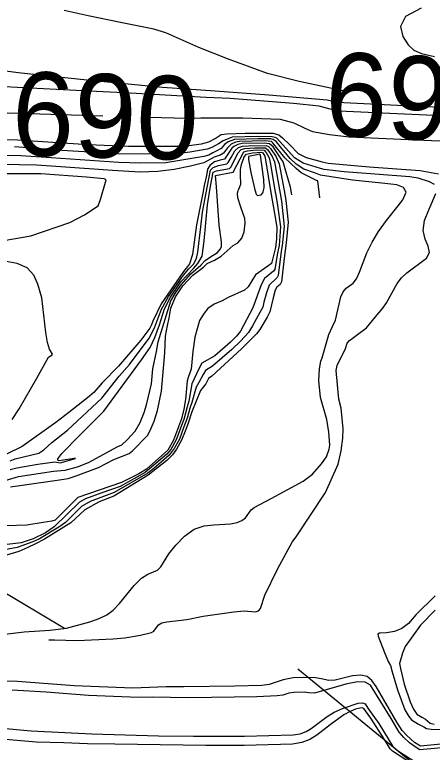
# Model space of a CAD drawing. Extents: x -291892836 to 2945206, y -477993085 to 1832792.
# Drawn here: x 1851369.4 to 1851534.2, y 543622.8 to 543914.3 of the extents above; entities that cross this region are included whole.
import ezdxf

# ---------------------------------------------------------------- set-up
doc = ezdxf.new("R2010")
doc.units = 0
for name, color, linetype in [('DT_X_Contour_Minor', 7, 'Continuous'), ('DT_X_Terrain_Ground_Line', 7, 'Continuous'), ('Level 40', 7, 'Continuous')]:
    doc.layers.add(name, color=color, linetype=linetype)

msp = doc.modelspace()

# ---------------------------------------------------------------- linework, layer by layer
at = {"layer": 'DT_X_Contour_Minor'}
for points in [[(1851499.24, 543884.15), (1851498.43, 543884.28), (1851481.72, 543887.85), (1851469.17, 543891.03), (1851453.37, 543896.84), (1851442.11, 543901.34), (1851429.09, 543907.13), (1851424.28, 543908.53), (1851411.18, 543911.22), (1851398.39, 543913.88), (1851388.86, 543916)], [(1851529.81, 543916.92), (1851523.71, 543913.53), (1851521.69, 543909.57), (1851522.58, 543905.62), (1851524.73, 543902.37), (1851526.95, 543900.3), (1851530, 543898.99), (1851535.11, 543897.8)], [(1851546.78, 543877.22), (1851528.41, 543878.01), (1851496.64, 543879.6), (1851492.72, 543880.44), (1851469.69, 543882.49), (1851448.55, 543884.11), (1851427.74, 543885.52), (1851397.89, 543888.44), (1851370.79, 543891.24), (1851356.01, 543893.23), (1851348.91, 543894.66), (1851336.31, 543898.35), (1851330.82, 543899.96), (1851325.81, 543901.03), (1851316.66, 543902.01), (1851302.47, 543902.95), (1851288.79, 543907.83), (1851276.02, 543912.01)], [(1851546.26, 543873.94), (1851523.28, 543874.9), (1851497.4, 543876.18), (1851494, 543876.89), (1851489.54, 543878.1), (1851479.49, 543879.12), (1851454.46, 543881.19), (1851445.02, 543881.55), (1851415, 543883.26), (1851391.06, 543884.42), (1851360.06, 543886), (1851330.21, 543887.45), (1851313.39, 543888.38), (1851301.85, 543889.32), (1851295.7, 543890.62), (1851269.11, 543896.87), (1851262.08, 543897.3), (1851231.01, 543898.91), (1851216.03, 543900.01)], [(1851203.38, 543886.9), (1851230.06, 543885.46), (1851256.87, 543883.74), (1851264.27, 543883.01), (1851286.17, 543879.69), (1851304.49, 543876.97), (1851328.42, 543876.52), (1851353.29, 543875.93), (1851383.7, 543874.97), (1851404.21, 543874.35)], [(1851422.2, 543873.82), (1851437.47, 543873.39), (1851442.92, 543873.48), (1851459.41, 543873.5), (1851474.2, 543872.93), (1851479.64, 543871.58), (1851483.96, 543869.49), (1851486.91, 543868.14), (1851493.62, 543866.9), (1851501.44, 543866.04), (1851527.63, 543864.81), (1851556.89, 543863.63), (1851580.1, 543862.15), (1851593.52, 543861.48), (1851622.96, 543860), (1851638.95, 543859.16)], [(1851348.82, 543865.07), (1851370.5, 543864.84), (1851398.35, 543862.93), (1851414.35, 543862.26), (1851436.11, 543862.29), (1851443.17, 543863.28), (1851445.98, 543864), (1851448.49, 543865.32), (1851450.96, 543866.94), (1851453.12, 543867.2), (1851460.34, 543867.48), (1851471.44, 543867.5), (1851473.66, 543866.86), (1851475.16, 543865.63), (1851478.04, 543862.78), (1851481.25, 543859.41), (1851484.42, 543857.8), (1851490.74, 543856.08), (1851493.12, 543855.63), (1851509.38, 543854.1), (1851529.41, 543852.76), (1851536.67, 543851.36)], [(1851535.07, 543847.15), (1851533.22, 543848.27), (1851528.64, 543849.67), (1851525.39, 543850.22), (1851499.52, 543852.14), (1851491.55, 543853.06), (1851490.12, 543853.49), (1851483.25, 543855.59), (1851479.89, 543857.68), (1851472.88, 543865.42), (1851472.2, 543865.8), (1851471.05, 543866.03), (1851465.35, 543866.14), (1851455.21, 543865.91), (1851451.7, 543864.44), (1851449.88, 543863.26), (1851447.26, 543861.75), (1851445.34, 543861.17), (1851438.51, 543859.95), (1851432.3, 543859.14), (1851410.01, 543859.28), (1851387.95, 543860.65), (1851369.25, 543862.09)], [(1851520.79, 543838.72), (1851522.67, 543841.08), (1851524.01, 543844.12), (1851522.95, 543846.02), (1851520.25, 543847.01), (1851514.3, 543847.74), (1851502.69, 543848.89), (1851490.06, 543850.88), (1851488.12, 543851.66), (1851483.6, 543853.27), (1851480.55, 543855.26), (1851478.14, 543857.48), (1851474.38, 543862.1), (1851472.63, 543864.13), (1851471.46, 543864.96), (1851470.45, 543865.16), (1851465.44, 543865.26), (1851456.22, 543865), (1851453.73, 543863.97), (1851452.27, 543862.94), (1851450.84, 543861.4), (1851448.97, 543860.37), (1851447.57, 543859.73), (1851446, 543858.78), (1851444.1, 543858.28), (1851429.07, 543855.71), (1851419.11, 543855.61), (1851410.44, 543855.88), (1851383.82, 543857.74), (1851371.75, 543858.47), (1851347.29, 543858.87)], [(1851489.8, 543841.96), (1851489.01, 543848.62), (1851488.58, 543848.69), (1851482.52, 543851.79), (1851480.53, 543853.44), (1851475.98, 543857.76), (1851471.22, 543863.83), (1851470.71, 543864.13), (1851468.19, 543864.37), (1851458.17, 543864.21), (1851456.55, 543863.89), (1851454.84, 543863.09), (1851453.37, 543861.71), (1851451.8, 543859.54), (1851450.48, 543858.77), (1851448.08, 543857.97), (1851444.05, 543855.67), (1851438.82, 543854.44), (1851432.35, 543853.04), (1851425.85, 543852.28), (1851418.76, 543852.05), (1851408.04, 543852.66), (1851387.61, 543854.16), (1851377.93, 543854.83), (1851364.35, 543855.07)], [(1851478.76, 543843.11), (1851478.3, 543846.06), (1851476.46, 543852.43), (1851475.43, 543856.17), (1851471.38, 543862.03), (1851469.96, 543863.29), (1851467.85, 543863.49), (1851459.2, 543863.31), (1851457.53, 543862.99), (1851455.95, 543862.22), (1851455.17, 543861.49), (1851452.17, 543857.24), (1851450.47, 543856.73), (1851448.28, 543856.06), (1851446.44, 543854.73), (1851445.47, 543853.22), (1851445.06, 543850.76), (1851444.23, 543846.72)], [(1851445.48, 543846.59), (1851446.65, 543852.88), (1851447.73, 543853.9), (1851449.91, 543854.66), (1851453.17, 543855.38), (1851453.73, 543855.82), (1851454.87, 543857.83), (1851456.32, 543860.5), (1851457.79, 543861.82), (1851459.26, 543862.27), (1851461.64, 543862.51), (1851468.63, 543862.56), (1851469.56, 543862.25), (1851470.36, 543861.43), (1851472.62, 543858.08), (1851473.78, 543855.27), (1851476.01, 543843.4)], [(1851446.74, 543846.46), (1851447.7, 543852.06), (1851449.08, 543852.6), (1851454.16, 543853.53), (1851454.69, 543853.96), (1851455.87, 543856.31), (1851457.48, 543859.52), (1851458.82, 543860.94), (1851460.28, 543861.37), (1851464.15, 543861.7), (1851468.47, 543861.61), (1851469.34, 543860.84), (1851471.05, 543858.29), (1851471.94, 543856.13), (1851474.18, 543843.59)], [(1851449.06, 543846.22), (1851448.73, 543850.74), (1851455.66, 543852.1), (1851459.85, 543860.07), (1851461.29, 543860.46), (1851464.71, 543860.82), (1851467.9, 543860.67), (1851468.64, 543859.82), (1851469.86, 543857.76), (1851470.29, 543855.92), (1851472.25, 543844.12), (1851472.3, 543843.79)], [(1851457.82, 543845.3), (1851458.61, 543847.28), (1851458.54, 543851.01), (1851458.54, 543853.11), (1851458.89, 543855.12), (1851460.03, 543858.14), (1851460.89, 543859.22), (1851463.33, 543859.72), (1851466.82, 543859.96), (1851467.3, 543859.65), (1851468.12, 543858.32), (1851468.43, 543856.89), (1851470.56, 543843.97)], [(1851467.51, 543844.29), (1851467.86, 543845.8), (1851467.76, 543849.11), (1851466.42, 543858.73), (1851466.17, 543859.1), (1851464.36, 543858.82), (1851461.64, 543858.21), (1851461.63, 543857.11), (1851462.6, 543851.95), (1851464.2, 543845.08), (1851464.35, 543844.62)], [(1851361.99, 543824.55), (1851375.73, 543826.84), (1851391.11, 543832.1), (1851396.89, 543835.22), (1851402.34, 543838.75), (1851403.32, 543841.22), (1851405.55, 543848.96), (1851404.75, 543849.45), (1851397.75, 543850.09), (1851379.66, 543851.34), (1851366.43, 543851.37)], [(1851361.15, 543728.84), (1851370.91, 543731.78), (1851384.68, 543733.83), (1851389.33, 543734.21), (1851394.24, 543735.62), (1851398.51, 543737.35), (1851401.74, 543739.02), (1851409.81, 543743.52), (1851411.67, 543744.32), (1851413.77, 543746.26), (1851416.96, 543749.7), (1851418.92, 543753.14), (1851420.51, 543757.09), (1851421.39, 543760.03), (1851423.41, 543768.35), (1851423.95, 543774.28), (1851425.34, 543781.1), (1851425.98, 543784.96), (1851430.99, 543801.16), (1851433.17, 543804.76), (1851435.09, 543807.55), (1851438.99, 543811.9), (1851442.89, 543815.31), (1851444.52, 543817.11), (1851446.65, 543818.64), (1851449.5, 543820.35), (1851450.64, 543821.77), (1851451.01, 543822.6), (1851450.99, 543824.52), (1851450.14, 543831.14), (1851449.06, 543846.22)], [(1851444.23, 543846.72), (1851443.63, 543843.8), (1851441.2, 543831.25), (1851439.56, 543819.49), (1851438.41, 543815.83), (1851437.67, 543814.8), (1851436.06, 543812.79), (1851427.22, 543800), (1851423.91, 543793.15), (1851423.42, 543791.73), (1851422.7, 543790.43), (1851419.12, 543785.7), (1851410.38, 543775.3), (1851403.9, 543768.72), (1851400.65, 543764.95), (1851398.18, 543762.83), (1851390.79, 543757.08), (1851385.56, 543753.06), (1851372.37, 543743.6), (1851366.16, 543740.65)], [(1851367.55, 543734.48), (1851370.2, 543735.19), (1851378.47, 543736.68), (1851385.28, 543737.59), (1851387.4, 543737.22), (1851393.41, 543738.87), (1851392.81, 543738.89), (1851386.9, 543737.93), (1851386.36, 543738.18), (1851386.4, 543738.79), (1851388, 543740.87), (1851394.79, 543747.77), (1851404.56, 543757.63), (1851419.43, 543777.86), (1851422.85, 543782.73), (1851424.66, 543786.64), (1851426.52, 543791.69), (1851428.54, 543798.04), (1851430.9, 543802.65), (1851435.04, 543808.67), (1851439.95, 543814.02), (1851441.69, 543815.95), (1851443.43, 543818.87), (1851444.14, 543824.84), (1851445.49, 543839.14), (1851446.74, 543846.46)], [(1851367.58, 543737.99), (1851369.62, 543738.71), (1851378.88, 543740.97), (1851380.87, 543742.26), (1851384.11, 543745.16), (1851390.28, 543750.11), (1851403.77, 543762.72), (1851410.65, 543771.46), (1851414.68, 543776.07), (1851422.49, 543786.39), (1851424.55, 543790.51), (1851427.3, 543797.89), (1851430.09, 543802.91), (1851436.06, 543811.28), (1851438.2, 543813.85), (1851439.93, 543815.66), (1851441.14, 543817.95), (1851441.69, 543820.43), (1851442.87, 543830.44), (1851443.56, 543836.17), (1851445.48, 543846.59)], [(1851367.7, 543727.61), (1851386.2, 543730.35), (1851390.56, 543731.03), (1851393.67, 543731.96), (1851402.47, 543735.36), (1851408.53, 543738.43), (1851414.62, 543740.9), (1851415.86, 543741.94), (1851421.76, 543747.91), (1851422.93, 543749.95), (1851424.48, 543753.64), (1851425.82, 543757.84), (1851427.4, 543765.55), (1851428.64, 543780.6), (1851428.99, 543787.27), (1851429.75, 543791.43), (1851430.35, 543794.38), (1851431.01, 543798.33), (1851432.88, 543802.74), (1851435.74, 543807.13), (1851439.72, 543811.27), (1851443.96, 543814.51), (1851445.44, 543815.91), (1851448.23, 543817.26), (1851450.91, 543818.8), (1851455.58, 543823.01), (1851457.47, 543824.12), (1851459.01, 543825.94), (1851459.95, 543828.45), (1851460.43, 543831.83), (1851460.25, 543833.68), (1851458.7, 543838.26), (1851457.46, 543841.96), (1851457.29, 543843.56), (1851457.62, 543844.82), (1851457.82, 543845.3)], [(1851474.18, 543843.59), (1851474.71, 543840.63), (1851475.78, 543830.58), (1851475, 543823.03), (1851474.64, 543820.79), (1851473.37, 543811.15), (1851473.02, 543810.4), (1851469.88, 543807.42), (1851468.77, 543804.34), (1851467.8, 543800.6), (1851467.3, 543798.62), (1851466.13, 543796.54), (1851463.31, 543791.29), (1851461.66, 543788.64), (1851458.6, 543785.27), (1851455.06, 543781.98), (1851447.46, 543775.34), (1851444.74, 543773.68), (1851443.86, 543772.13), (1851442.08, 543768.88), (1851441, 543767.03), (1851439.33, 543761.02), (1851438.54, 543758.82), (1851437.45, 543754.86), (1851436.2, 543751.37), (1851434.39, 543746.56), (1851432.39, 543742.84), (1851430.33, 543740.19), (1851424.31, 543734.92), (1851421.97, 543733.11), (1851408.64, 543725.46), (1851399.16, 543721.9), (1851395.79, 543719.89), (1851389.47, 543713.59), (1851386.8, 543711.69), (1851379.23, 543707.11), (1851376.6, 543705.91), (1851370.39, 543703.68), (1851360.22, 543701.91)], [(1851476.01, 543843.4), (1851476.48, 543840.89), (1851477.37, 543832.22), (1851476.51, 543824.1), (1851475.79, 543817.99), (1851474.69, 543808.73), (1851474.14, 543807.6), (1851472.83, 543806.54), (1851472.24, 543805.41), (1851471.38, 543802.43), (1851470.11, 543796.84), (1851469.01, 543794.74), (1851466.11, 543789.9), (1851464.83, 543788.08), (1851458.93, 543782.2), (1851447.17, 543771.42), (1851445.96, 543770.48), (1851444.8, 543768.43), (1851442.74, 543765.74), (1851439.33, 543757.31), (1851437.7, 543752.46), (1851436.71, 543749.74), (1851435.26, 543746.14), (1851433.24, 543742.51), (1851431.66, 543740.38), (1851429.4, 543738.1), (1851422.12, 543732.31), (1851408.47, 543723.95), (1851402.78, 543721.79), (1851397.01, 543718.58), (1851391.57, 543713.49), (1851381.11, 543707.05), (1851377.59, 543705.15), (1851374.57, 543703.72), (1851370.96, 543702.12), (1851361.2, 543699.18)], [(1851470.56, 543843.97), (1851471.94, 543835.68), (1851472.84, 543830.27), (1851472.77, 543825.74), (1851472.39, 543822.22), (1851470.72, 543816), (1851469.39, 543814.83), (1851464.48, 543811.4), (1851461.52, 543806.75), (1851460.05, 543805.44), (1851453.7, 543802.44), (1851451.32, 543801.18), (1851448.08, 543799.84), (1851445.69, 543798.13), (1851444.17, 543796.36), (1851442.4, 543793.4), (1851441.72, 543791.02), (1851440.56, 543786.83), (1851439.7, 543781.15), (1851439.02, 543774.16), (1851437.95, 543771.34), (1851437.54, 543769.61), (1851436.84, 543762.16), (1851436.1, 543758.37), (1851435.19, 543754.61), (1851432.08, 543746.16), (1851429.8, 543742.16), (1851421.42, 543734.71), (1851418.4, 543732.77), (1851411.53, 543729.44), (1851402.71, 543726.37), (1851394.36, 543723.42), (1851393.68, 543722.82), (1851385.3, 543714.47), (1851384.08, 543714.17), (1851380.6, 543713.62), (1851374.23, 543712.53), (1851366.16, 543712.26)], [(1851472.3, 543843.79), (1851473.14, 543838.86), (1851474.31, 543830.42), (1851473.81, 543823.03), (1851473.13, 543820.22), (1851472.04, 543813.57), (1851471.61, 543812.91), (1851468.01, 543810.03), (1851466.7, 543807.49), (1851463.43, 543798.39), (1851458.49, 543789.21), (1851456.94, 543787.26), (1851454.61, 543784.83), (1851448.41, 543779.43), (1851443.29, 543776.56), (1851442.02, 543774.31), (1851439.27, 543768.32), (1851438.09, 543761.59), (1851437.45, 543759.35), (1851436.19, 543754.35), (1851435.7, 543752.99), (1851433.19, 543746.28), (1851431.08, 543742.42), (1851429.45, 543740.6), (1851420.84, 543733.31), (1851411, 543727.84), (1851403.77, 543725.26), (1851397.32, 543722.92), (1851395.02, 543721.64), (1851385.03, 543711.91), (1851381.49, 543709.55), (1851376.69, 543707.06), (1851371.92, 543705.58), (1851366.46, 543704.87)], [(1851464.35, 543844.62), (1851464.77, 543843.35), (1851465.25, 543842.77), (1851466.63, 543843.03), (1851467.41, 543843.86), (1851467.51, 543844.29)], [(1851532.97, 543837.45), (1851535.64, 543843.63)], [(1851382.91, 543667.2), (1851385.15, 543667.22), (1851394.03, 543666.95), (1851408.23, 543667.58), (1851412.93, 543667.97), (1851419.09, 543669.01), (1851423.42, 543670.07), (1851424.34, 543670.57), (1851426.19, 543673.1), (1851427.51, 543673.88), (1851429.51, 543674.31), (1851437.39, 543675.29), (1851443.8, 543676.61), (1851455.87, 543678.22), (1851459.95, 543678.61), (1851464.44, 543678.28), (1851465.69, 543678.61), (1851466.42, 543679.57), (1851468.08, 543684.82), (1851473.33, 543695.4), (1851479, 543705.87), (1851480.84, 543708.32), (1851492.08, 543725.38), (1851497.09, 543736.62), (1851498.29, 543741.93), (1851499, 543746.87), (1851499.01, 543750.59), (1851498.25, 543758.75), (1851497.32, 543762.3), (1851496.31, 543773.65), (1851496.71, 543775.65), (1851499.94, 543782.41), (1851500.67, 543784.41), (1851501.63, 543785.5), (1851504.76, 543787.94), (1851508.23, 543790.55), (1851511.88, 543794.91), (1851514.78, 543798.35), (1851516.22, 543800.43), (1851520.41, 543808.02), (1851522.16, 543810.22), (1851524.24, 543812.2), (1851531.96, 543818.1), (1851533.17, 543820.33), (1851532.67, 543822.79), (1851531.39, 543825.62), (1851530.6, 543829.01), (1851531.24, 543832.99), (1851532.83, 543837.12), (1851532.97, 543837.45)], [(1851432.98, 543704.68), (1851436.38, 543708.19), (1851440.2, 543710.91), (1851444.16, 543712.29), (1851448.03, 543712.71), (1851454.65, 543713.01), (1851457.17, 543713.53), (1851459.11, 543714.36), (1851460.49, 543715.46), (1851462.75, 543718.6), (1851463.97, 543719.52), (1851470.6, 543723.1), (1851483.26, 543729.9), (1851486.95, 543732.67), (1851490.56, 543736.74), (1851492.54, 543739.52), (1851493.57, 543742.52), (1851493.81, 543744.16), (1851493.35, 543749.28), (1851492.67, 543754.35), (1851490.17, 543762.99), (1851489.4, 543769.75), (1851489.74, 543774.35), (1851490.27, 543777.34), (1851490.79, 543778.64), (1851493.41, 543787.82), (1851494.83, 543791.03), (1851496.1, 543793.59), (1851498.09, 543802.71), (1851499.06, 543804.68), (1851500.24, 543806.22), (1851502.96, 543808.22), (1851504.3, 543809.83), (1851505.55, 543812.52), (1851508.44, 543820.14), (1851510.48, 543824.33), (1851513.04, 543828.59), (1851516.15, 543832.9), (1851520.79, 543838.72)], [(1851368.36, 543754.33), (1851371.17, 543758.46), (1851378.08, 543770.64), (1851382.73, 543778.96), (1851384.06, 543779.67), (1851384.33, 543780.15), (1851383.19, 543782.12), (1851382.33, 543784.66), (1851381.62, 543788.69), (1851380.04, 543802.36), (1851378.56, 543807.84), (1851376.94, 543811.32), (1851374.25, 543814.26), (1851370.38, 543816), (1851366.08, 543816.79)], [(1851357.86, 543668.46), (1851373.14, 543670.38), (1851383.28, 543671.01), (1851389.83, 543671.79), (1851399.08, 543674.34), (1851402.76, 543675.66), (1851405.75, 543677.12), (1851408.28, 543678.99), (1851410.8, 543681.58), (1851416.58, 543688.62), (1851419.43, 543691.52), (1851421.94, 543693.13), (1851425.74, 543694.71), (1851427.06, 543696.11), (1851430.27, 543701.14), (1851432.98, 543704.68)], [(1851535.43, 543684.58), (1851527.73, 543677.12), (1851524.8, 543673.63), (1851522.23, 543671.73), (1851519.31, 543670.52), (1851516.18, 543669.95), (1851513.46, 543669.84), (1851512.8, 543669.47), (1851512.85, 543668.63), (1851515.43, 543662.16), (1851516.8, 543658.67), (1851517.74, 543657.02), (1851518.47, 543654.56), (1851520.52, 543647.44), (1851523.43, 543639.56), (1851524.98, 543636.86), (1851526.11, 543635.54), (1851528.76, 543633.91), (1851530.92, 543632.84), (1851531.93, 543632.15), (1851533.78, 543631.94), (1851552.96, 543631.37)], [(1851535.36, 543678.97), (1851529.64, 543672.98), (1851523.51, 543664.6), (1851522.56, 543661.87), (1851521.36, 543657.8), (1851521.67, 543655.84), (1851523.15, 543649.72), (1851525.51, 543642.66), (1851526.78, 543639.84), (1851528.22, 543637.86), (1851530.11, 543636.68), (1851531.6, 543635.81), (1851533.44, 543634.31), (1851534.96, 543633.83)], [(1851541.73, 543626.32), (1851529.62, 543625.15), (1851527.19, 543626.69), (1851524.09, 543629.46), (1851522.32, 543631.35), (1851520.28, 543634.69), (1851512.13, 543648.78), (1851510.44, 543651.11), (1851508.51, 543652.66), (1851506.01, 543653.28), (1851502.73, 543652.91), (1851495.88, 543651.3), (1851493.41, 543651.12), (1851490.34, 543651.76), (1851488.19, 543652.21), (1851483.45, 543652.33), (1851479.33, 543652.13), (1851475.43, 543651.44), (1851469.8, 543649.5), (1851466.96, 543649.15), (1851456.24, 543648.86), (1851436.18, 543648.61), (1851429.24, 543648.61), (1851416.01, 543648.04), (1851392.89, 543648.97), (1851370.52, 543650.68), (1851354.12, 543651)], [(1851542.19, 543624.87), (1851529.4, 543623.78), (1851527.95, 543624.63), (1851525.28, 543626.52), (1851523.01, 543628.58), (1851521.16, 543630.75), (1851517.98, 543636.06), (1851509.85, 543649.25), (1851507.82, 543650.47), (1851504.67, 543650.64), (1851500.08, 543649.67), (1851487.74, 543646.12), (1851485.48, 543646.23), (1851483.67, 543646.52), (1851479.65, 543646.43), (1851477.58, 543646.06), (1851475.29, 543645.34), (1851473.03, 543645.02), (1851464.97, 543644.69), (1851438.18, 543644.29), (1851423.62, 543644.5), (1851418.28, 543644.39), (1851398.51, 543645.15), (1851381.76, 543646.48), (1851368.34, 543647.37)], [(1851348.5, 543633.68), (1851375.93, 543631.27), (1851399.87, 543630.04), (1851426.16, 543629.24), (1851440, 543629.08), (1851460.05, 543629.16), (1851479.3, 543629.61), (1851482.07, 543630.04), (1851484.4, 543630.93), (1851486.41, 543632.18), (1851492.7, 543636.93), (1851495.52, 543638.57), (1851498.85, 543640.11), (1851504.99, 543642.14), (1851506.74, 543642.29), (1851507.7, 543641.92), (1851508.86, 543640.26), (1851510.74, 543637.4), (1851513.1, 543634.12), (1851518.69, 543625.05), (1851520.94, 543623.14), (1851528.51, 543618.3)], [(1851528, 543617.03), (1851518.51, 543623.26), (1851517.62, 543624.17), (1851515.34, 543627.75), (1851510.04, 543636.24), (1851507.86, 543639.13), (1851507.19, 543640.09), (1851506.63, 543640.3), (1851505.63, 543640.22), (1851504, 543639.75), (1851501.85, 543638.85), (1851499.35, 543637.5), (1851493.9, 543633.62), (1851488.64, 543629.46), (1851485.93, 543627.77), (1851482.79, 543626.58), (1851479.06, 543626), (1851460.03, 543625.46), (1851444.83, 543625.43), (1851417.91, 543625.83), (1851408.97, 543625.97), (1851398.18, 543626.11), (1851388.72, 543626.46), (1851377.91, 543626.76), (1851364.36, 543627.89)]]:
    msp.add_lwpolyline(points, dxfattribs=at)
at = {"layer": 'Level 40'}
for p, q in [((1851210.63, 543778.33), (1851389.11, 543671.79)), ((1851676.91, 543495.5), (1851481.19, 543655.61))]:
    msp.add_line(p, q, dxfattribs=at)

# ---------------------------------------------------------------- texts
at = {"layer": 'DT_X_Terrain_Ground_Line'}
for s, rotation, p in [('695', 357.1418, (1851491.33, 543866.74)), ('690', 358.3507, (1851367.92, 543858.88))]:
    msp.add_text(s, height=33, rotation=rotation, dxfattribs=at).set_placement(p)

doc.saveas('drawing.dxf')
